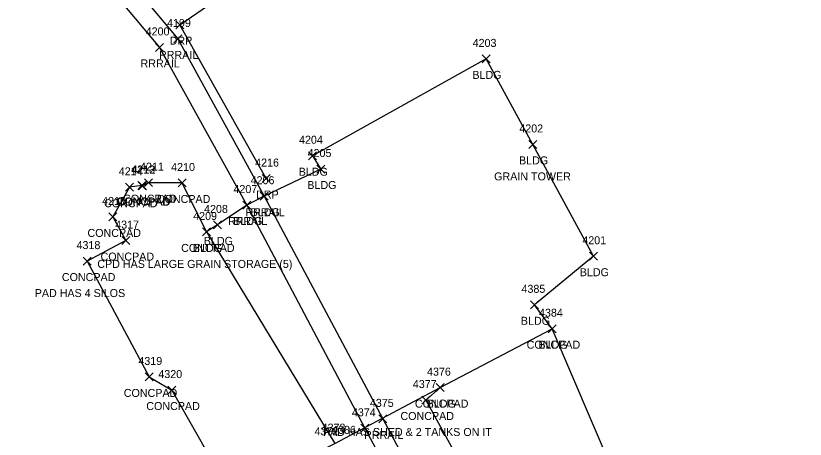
# Model space of a CAD drawing. Extents: x 1462668 to 1465147, y 550359 to 557351.
# Drawn here: x 1463750.3 to 1463947.5, y 555606.3 to 555712.3 of the extents above; entities that cross this region are included whole.
import ezdxf

# ---------------------------------------------------------------- set-up
doc = ezdxf.new("R2010")
doc.units = 0
for name, color, linetype in [('L_A', 7, 'Continuous'), ('L_C', 7, 'Continuous'), ('L_I', 7, 'Continuous'), ('L_TIC', 7, 'Continuous'), ('LBC', 7, 'Continuous'), ('LS', 7, 'Continuous'), ('P_I', 7, 'Continuous'), ('R_A', 7, 'Continuous'), ('R_I', 7, 'Continuous'), ('R_TIC', 7, 'Continuous'), ('RDP', 7, 'Continuous'), ('RR', 7, 'Continuous')]:
    doc.layers.add(name, color=color, linetype=linetype)

msp = doc.modelspace()

# ---------------------------------------------------------------- linework, layer by layer
at = {"layer": 'L_TIC'}
for points in [[(1463866.76, 555700.48), (1463868.76, 555702.48)], [(1463868.76, 555700.48), (1463866.76, 555702.48)], [(1463878.42, 555679.08), (1463880.42, 555681.08)], [(1463880.42, 555679.08), (1463878.42, 555681.08)], [(1463823.37, 555676.25), (1463825.37, 555678.25)], [(1463825.37, 555676.25), (1463823.37, 555678.25)], [(1463825.52, 555672.92), (1463827.52, 555674.92)], [(1463827.52, 555672.92), (1463825.52, 555674.92)], [(1463777.7, 555668.36), (1463779.7, 555670.36)], [(1463779.7, 555668.36), (1463777.7, 555670.36)], [(1463780.79, 555668.81), (1463782.79, 555670.81)], [(1463782.79, 555668.81), (1463780.79, 555670.81)], [(1463780.91, 555668.74), (1463782.91, 555670.74)], [(1463782.91, 555668.74), (1463780.91, 555670.74)], [(1463782.44, 555669.51), (1463784.44, 555671.51)], [(1463784.44, 555669.51), (1463782.44, 555671.51)], [(1463790.86, 555669.43), (1463792.86, 555671.43)], [(1463792.86, 555669.43), (1463790.86, 555671.43)], [(1463811.34, 555666.12), (1463813.34, 555668.12)], [(1463813.34, 555666.12), (1463811.34, 555668.12)], [(1463806.99, 555663.91), (1463808.99, 555665.91)], [(1463808.99, 555663.91), (1463806.99, 555665.91)], [(1463773.53, 555660.93), (1463775.53, 555662.93)], [(1463775.53, 555660.93), (1463773.53, 555662.93)], [(1463799.65, 555658.94), (1463801.65, 555660.94)], [(1463801.65, 555658.94), (1463799.65, 555660.94)], [(1463796.93, 555657.18), (1463798.93, 555659.18)], [(1463798.93, 555657.18), (1463796.93, 555659.18)], [(1463796.93, 555657.18), (1463798.93, 555659.18)], [(1463798.93, 555657.18), (1463796.93, 555659.18)], [(1463776.8, 555655.02), (1463778.8, 555657.02)], [(1463778.8, 555655.02), (1463776.8, 555657.02)], [(1463893.59, 555651.1), (1463895.59, 555653.1)], [(1463895.59, 555651.1), (1463893.59, 555653.1)], [(1463893.59, 555651.1), (1463895.59, 555653.1)], [(1463895.59, 555651.1), (1463893.59, 555653.1)], [(1463767.14, 555649.89), (1463769.14, 555651.89)], [(1463769.14, 555649.89), (1463767.14, 555651.89)], [(1463878.88, 555638.95), (1463880.88, 555640.95)], [(1463880.88, 555638.95), (1463878.88, 555640.95)], [(1463878.88, 555638.95), (1463880.88, 555640.95)], [(1463880.88, 555638.95), (1463878.88, 555640.95)], [(1463883.26, 555632.97), (1463885.26, 555634.97)], [(1463885.26, 555632.97), (1463883.26, 555634.97)], [(1463883.26, 555632.97), (1463885.26, 555634.97)], [(1463885.26, 555632.97), (1463883.26, 555634.97)], [(1463782.6, 555620.9), (1463784.6, 555622.9)], [(1463784.6, 555620.9), (1463782.6, 555622.9)], [(1463788.23, 555617.62), (1463790.23, 555619.62)], [(1463790.23, 555617.62), (1463788.23, 555619.62)], [(1463855.34, 555618.23), (1463857.34, 555620.23)], [(1463857.34, 555618.23), (1463855.34, 555620.23)], [(1463855.34, 555618.23), (1463857.34, 555620.23)], [(1463857.34, 555618.23), (1463855.34, 555620.23)], [(1463851.73, 555615.13), (1463853.73, 555617.13)], [(1463853.73, 555615.13), (1463851.73, 555617.13)]]:
    msp.add_lwpolyline(points, dxfattribs=at)
at = {"layer": 'LBC'}
for points in [[(1463894.59, 555652.1), (1463879.42, 555680.08), (1463867.76, 555701.48), (1463824.37, 555677.25), (1463826.52, 555673.92), (1463812.34, 555667.12), (1463807.99, 555664.91), (1463800.65, 555659.94), (1463797.93, 555658.18), (1463829.95, 555605.22), (1463856.34, 555619.23), (1463884.26, 555633.97), (1463879.88, 555639.95)], [(1463894.59, 555652.1), (1463879.88, 555639.95)]]:
    msp.add_lwpolyline(points, dxfattribs=at)
at = {"layer": 'LS'}
for points in [[(1463797.93, 555658.18), (1463791.86, 555670.43), (1463783.44, 555670.51), (1463781.91, 555669.74), (1463781.79, 555669.81), (1463778.7, 555669.36), (1463774.53, 555661.93), (1463777.8, 555656.02), (1463768.14, 555650.89), (1463783.6, 555621.9), (1463789.23, 555618.62), (1463805.91, 555589.26), (1463810.05, 555591.24), (1463812.93, 555586.67), (1463824.07, 555586.07), (1463830.3, 555573.41), (1463839.65, 555577.92), (1463828.17, 555604.3), (1463829.95, 555605.22)], [(1463856.34, 555619.23), (1463852.73, 555616.13), (1463862.3, 555598.7), (1463866.26, 555600.59), (1463869.31, 555593.66), (1463873.74, 555582.79), (1463900.51, 555593.51), (1463899.27, 555598.83), (1463884.26, 555633.97)]]:
    msp.add_lwpolyline(points, dxfattribs=at)
at = {"layer": 'R_TIC'}
for points in [[(1463790.22, 555709.04), (1463792.22, 555711.04)], [(1463792.22, 555709.04), (1463790.22, 555711.04)], [(1463789.76, 555705.47), (1463791.76, 555707.47)], [(1463791.76, 555705.47), (1463789.76, 555707.47)], [(1463785.15, 555703.35), (1463787.15, 555705.35)], [(1463787.15, 555703.35), (1463785.15, 555705.35)], [(1463811.83, 555670.54), (1463813.83, 555672.54)], [(1463813.83, 555670.54), (1463811.83, 555672.54)], [(1463811.34, 555666.12), (1463813.34, 555668.12)], [(1463813.34, 555666.12), (1463811.34, 555668.12)], [(1463806.99, 555663.91), (1463808.99, 555665.91)], [(1463808.99, 555663.91), (1463806.99, 555665.91)], [(1463841, 555610.41), (1463843, 555612.41)], [(1463843, 555610.41), (1463841, 555612.41)], [(1463836.51, 555608.05), (1463838.51, 555610.05)], [(1463838.51, 555608.05), (1463836.51, 555610.05)]]:
    msp.add_lwpolyline(points, dxfattribs=at)
at = {"layer": 'RDP'}
msp.add_lwpolyline([(1463812.83, 555671.54), (1463791.22, 555710.04), (1463806.68, 555720.66), (1463816.08, 555736.12), (1463819.91, 555746.72), (1463821.55, 555766.99)], dxfattribs=at)
at = {"layer": 'RR'}
for points in [[(1463564.15, 556052.98), (1463577.63, 556016.16), (1463590.5, 555985.5), (1463604.09, 555955.34), (1463621.74, 555920.66), (1463640.97, 555887.98), (1463659.02, 555863.36), (1463674.56, 555844.98), (1463790.76, 555706.47), (1463812.34, 555667.12), (1463842, 555611.41), (1463880.6, 555538.7), (1463906.31, 555490.4), (1463925.67, 555454.53), (1463964.21, 555382.49), (1463992.77, 555329.44)], [(1463559.44, 556051.72), (1463573.12, 556014.32), (1463586.06, 555983.65), (1463600.11, 555952.4), (1463617.47, 555918.22), (1463637.11, 555885.1), (1463655.59, 555859.72), (1463671.73, 555840.87), (1463786.15, 555704.35), (1463807.99, 555664.91), (1463837.51, 555609.05), (1463871.83, 555544.68), (1463902.36, 555487.74), (1463921.15, 555452.57), (1463959.81, 555380.31), (1463988.19, 555327.21)]]:
    msp.add_lwpolyline(points, dxfattribs=at)

# ---------------------------------------------------------------- texts
at = {"layer": 'L_A'}
for s, p in [('BLDG', (1463864.35, 555696.48)), ('BLDG', (1463876.01, 555675.08)), ('BLDG', (1463820.96, 555672.25)), ('BLDG', (1463823.11, 555668.92)), ('CONCPAD', (1463772.34, 555664.36)), ('CONCPAD', (1463775.43, 555664.81)), ('CONCPAD', (1463775.55, 555664.74)), ('CONCPAD', (1463777.08, 555665.51)), ('CONCPAD', (1463785.51, 555665.43)), ('BLDG', (1463808.93, 555662.12)), ('BLDG', (1463804.58, 555659.91)), ('CONCPAD', (1463768.18, 555656.93)), ('BLDG', (1463797.24, 555654.94)), ('CONCPAD', (1463791.58, 555653.18)), ('BLDG', (1463794.52, 555653.18)), ('CONCPAD', (1463771.45, 555651.02)), ('BLDG', (1463891.18, 555647.1)), ('BLDG', (1463891.18, 555647.1)), ('CONCPAD', (1463761.78, 555645.89)), ('BLDG', (1463876.47, 555634.95)), ('BLDG', (1463876.47, 555634.95)), ('CONCPAD', (1463877.91, 555628.97)), ('BLDG', (1463880.85, 555628.97)), ('CONCPAD', (1463777.25, 555616.9)), ('CONCPAD', (1463782.88, 555613.62)), ('CONCPAD', (1463849.99, 555614.23)), ('BLDG', (1463852.93, 555614.23)), ('CONCPAD', (1463846.38, 555611.13))]:
    msp.add_text(s, height=2, dxfattribs=at).set_placement(p)
at = {"layer": 'L_C'}
for s, p in [('GRAIN TOWER', (1463869.79, 555671.08)), ('CPD HAS LARGE GRAIN STORAGE (5)', (1463770.64, 555649.18)), ('PAD HAS 4 SILOS', (1463755, 555641.89)), ('PAD HAS SHED & 2 TANKS ON IT', (1463827.02, 555607.13))]:
    msp.add_text(s, height=2, dxfattribs=at).set_placement(p)
at = {"layer": 'L_I'}
for s, p in [('4203', (1463864.42, 555704.48)), ('4202', (1463876.08, 555683.08)), ('4204', (1463821.04, 555680.25)), ('4205', (1463823.18, 555676.92)), ('4214', (1463776, 555672.36)), ('4213', (1463779.1, 555672.81)), ('4212', (1463779.21, 555672.74)), ('4211', (1463781.31, 555673.51)), ('4210', (1463789.09, 555673.43)), ('4206', (1463808.95, 555670.12)), ('4207', (1463804.65, 555667.91)), ('4215', (1463771.84, 555664.93)), ('4208', (1463797.31, 555662.94)), ('4209', (1463794.59, 555661.18)), ('4209', (1463794.59, 555661.18)), ('4317', (1463775.11, 555659.02)), ('4201', (1463891.82, 555655.1)), ('4201', (1463891.82, 555655.1)), ('4318', (1463765.45, 555653.89)), ('4385', (1463876.62, 555642.95)), ('4385', (1463876.62, 555642.95)), ('4384', (1463881, 555636.97)), ('4384', (1463881, 555636.97)), ('4319', (1463780.9, 555624.9)), ('4320', (1463785.89, 555621.62)), ('4376', (1463853.02, 555622.23)), ('4376', (1463853.02, 555622.23)), ('4377', (1463849.47, 555619.13)), ('4372', (1463824.91, 555607.3)), ('4373', (1463826.69, 555608.22)), ('4373', (1463826.69, 555608.22))]:
    msp.add_text(s, height=2, dxfattribs=at).set_placement(p)
at = {"layer": 'P_I'}
msp.add_text('4386', height=2, dxfattribs=at).set_placement((1463829.29, 555607.66))
at = {"layer": 'R_A'}
for s, p in [('DRP', (1463788.71, 555705.04)), ('RRRAIL', (1463786.05, 555701.47)), ('RRRAIL', (1463781.44, 555699.35)), ('DRP', (1463810.32, 555666.54)), ('RRRAIL', (1463807.63, 555662.12)), ('RRRAIL', (1463803.28, 555659.91)), ('RRRAIL', (1463837.29, 555606.41))]:
    msp.add_text(s, height=2, dxfattribs=at).set_placement(p)
at = {"layer": 'R_I'}
for s, p in [('4199', (1463788.06, 555709.47)), ('4200', (1463782.72, 555707.35)), ('4216', (1463810.08, 555674.54)), ('4206', (1463808.95, 555670.12)), ('4207', (1463804.65, 555667.91)), ('4375', (1463838.74, 555614.41)), ('4374', (1463834.25, 555612.05))]:
    msp.add_text(s, height=2, dxfattribs=at).set_placement(p)

doc.saveas('drawing.dxf')
